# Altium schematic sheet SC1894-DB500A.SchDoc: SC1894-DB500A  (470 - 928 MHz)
size B; Organization: Maxim Integrated; Address1: 160 Rio Robles; Address2: San Jose, CA. 95134; Address3: U.S.A.; Address4: 408-601-1000; Revision: 2.0; SheetNumber: 1; SheetTotal: 1; PageSetup: Record=PageOptions¦CenterHorizontal=True¦CenterVertical=True¦PrintScale=1.12¦XCorrection=1.00¦YCorrection=1.00¦PrintKind=1¦BorderSize=5000000¦LeftOffset=0¦BottomOffset=0¦Orientation=2¦PaperLength=1000¦PaperWidth=1000¦Scale=100¦PaperSource=15¦PrintQuality=600¦MediaType=1¦DitherType=10¦PaperKind=Tabloid¦PrintScaleMode=1
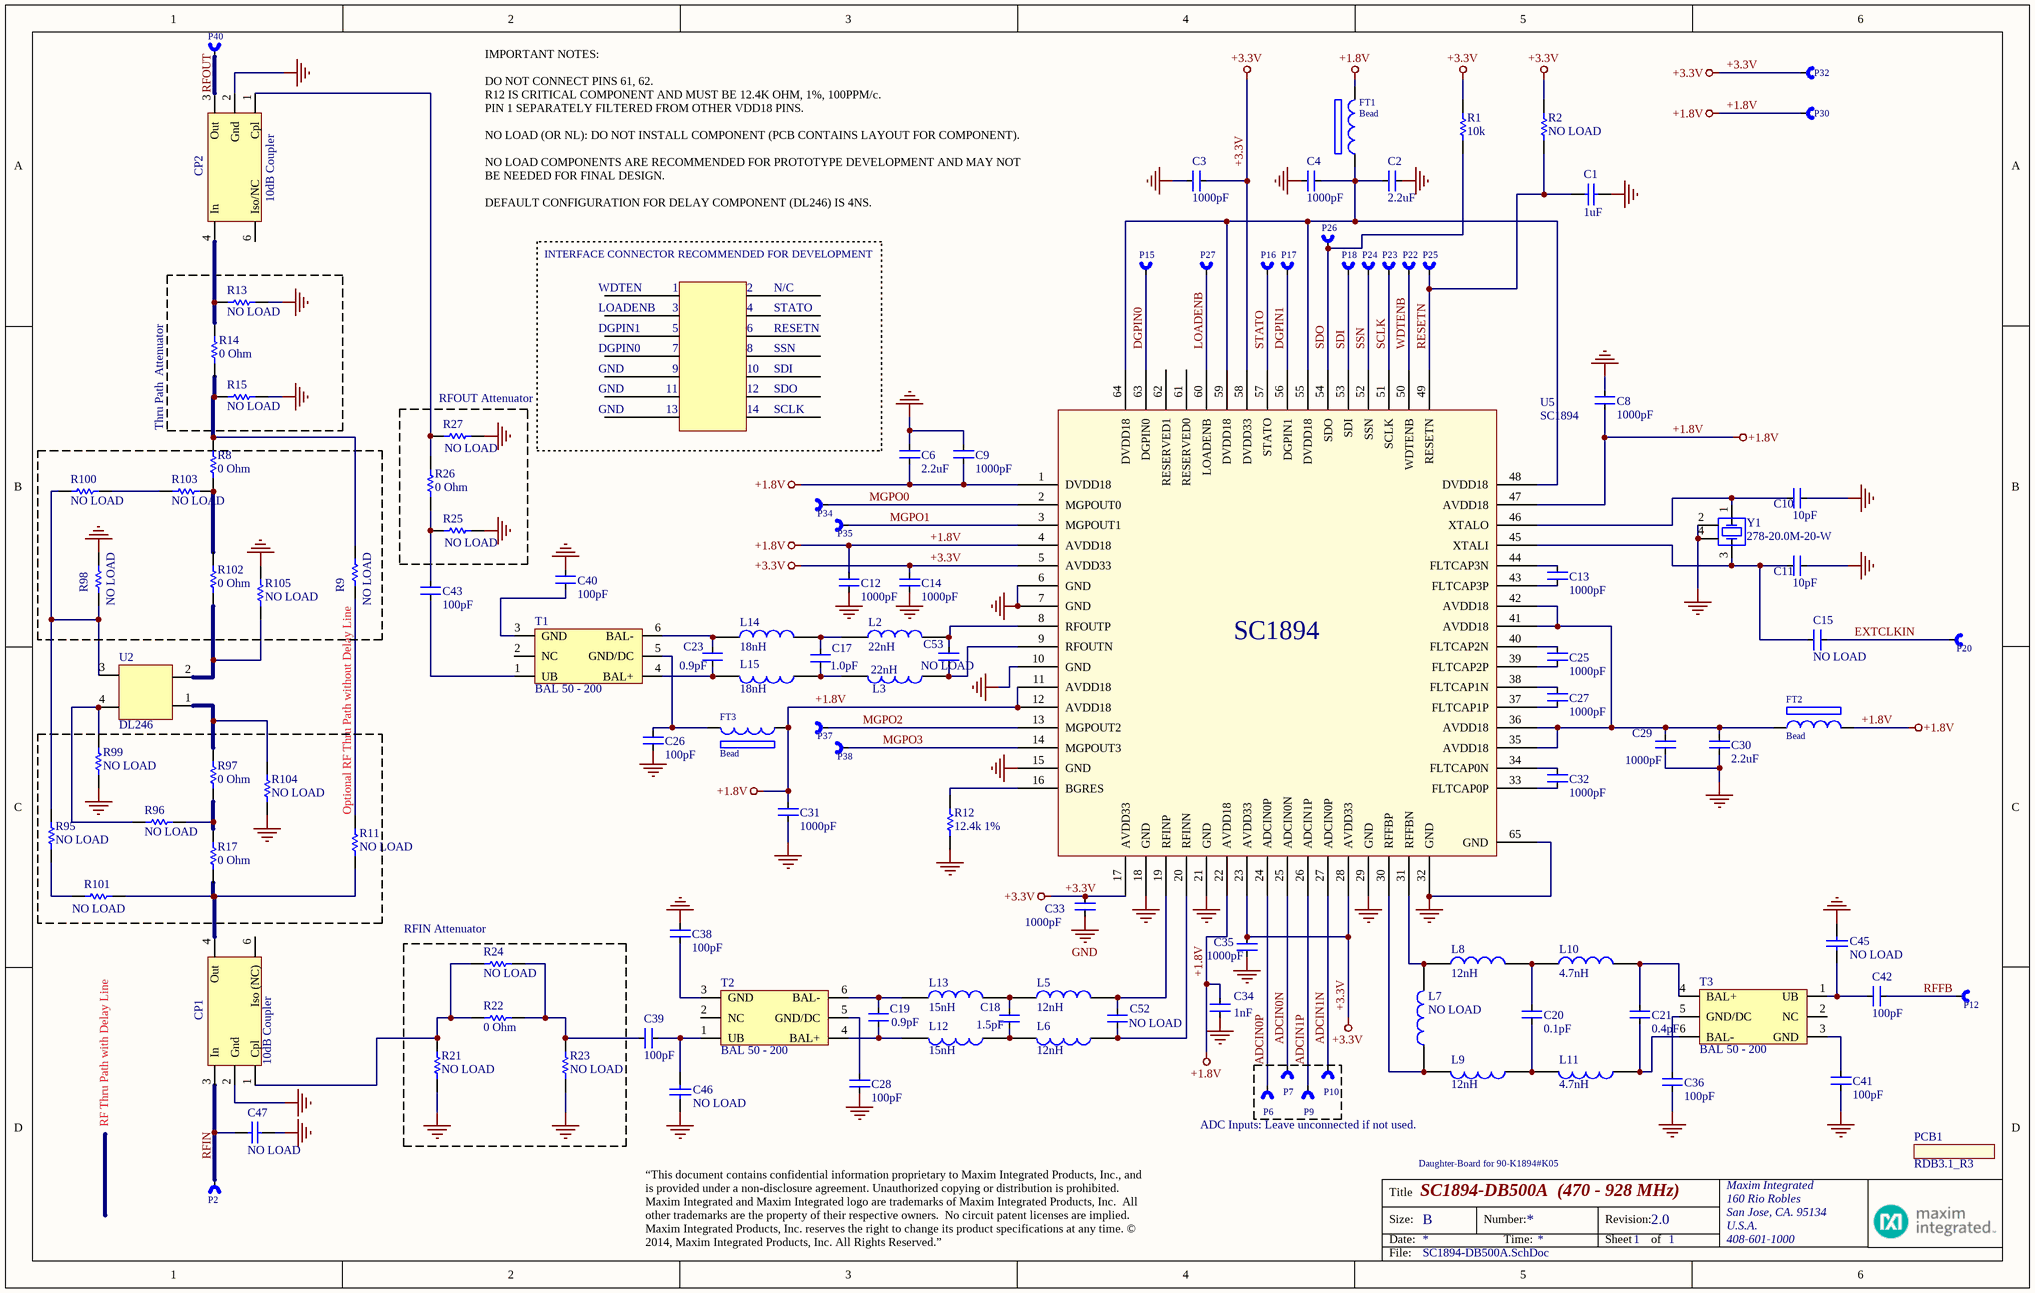
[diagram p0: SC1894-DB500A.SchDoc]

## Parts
C1  1uF  [1608[0603]]
C2  2.2uF  [0603 SMD]
C3  1000pF  [0402 SMD]
C4  1000pF  [0402 SMD]
C6  2.2uF  [0603 SMD]
C8  1000pF  [0402 SMD]
C9  1000pF  [0402 SMD]
C10  10pF  [0402 SMD]
C11  10pF  [0402 SMD]
C12  1000pF  [0402 SMD]
C13  1000pF  [0402 SMD]
C14  1000pF  [0402 SMD]
C15  NO LOAD  [0402 SMD]
C17  1.0pF  [0402 SMD]
C18  1.5pF  [0402 SMD]
C19  0.9pF  [0402 SMD]
C20  0.1pF  [0402 SMD]
C21  0.4pF  [0402 SMD]
C23  0.9pF  [0402 SMD]
C25  1000pF  [0402 SMD]
C26  100pF  [0402 SMD]
C27  1000pF  [0402 SMD]
C28  100pF  [0402 SMD]
C29  1000pF  [0402 SMD]
C30  2.2uF  [0603 SMD]
C31  1000pF  [0402 SMD]
C32  1000pF  [0402 SMD]
C33  1000pF  [0402 SMD]
C34  1nF  [0402 SMD]
C35  1000pF  [0402 SMD]
C36  100pF  [0402 SMD]
C38  100pF  [0402 SMD]
C39  100pF  [0402 SMD]
C40  100pF  [0402 SMD]
C41  100pF  [0402 SMD]
C42  100pF  [0402 SMD]
C43  100pF  [0402 SMD]
C45  NO LOAD  [0402 SMD]
C46  NO LOAD  [0402 SMD]
C47  NO LOAD  [0402 SMD]
C52  NO LOAD  [0402 SMD]
C53  NO LOAD  [0402 SMD]
CP1  10dB Coupler  [DBTC-10-13]
CP2  10dB Coupler  [DBTC-10-13]
FT1  Bead  [0603 SMD]
FT2  Bead  [0603 SMD]
FT3  Bead  [0402 SMD]
L2  22nH  [0402 SMD]
L3  22nH  [0402 SMD]
L5  12nH  [0402 SMD]
L6  12nH  [0402 SMD]
L7  NO LOAD  [0402 SMD]
L8  12nH  [0402 SMD]
L9  12nH  [0402 SMD]
L10  4.7nH  [0402 SMD]
L11  4.7nH  [0402 SMD]
L12  15nH  [0402 SMD]
L13  15nH  [0402 SMD]
L14  18nH  [0402 SMD]
L15  18nH  [0402 SMD]
P2  PORT 1-M  [PORT-1_M-PAD]  (value not drawn)
P6  PORT 1-M  [PORT-1_M-PAD]  (value not drawn)
P7  PORT 1-M  [PORT-1_M-PAD]  (value not drawn)
P9  PORT 1-M  [PORT-1_M-PAD]  (value not drawn)
P10  PORT 1-M  [PORT-1_M-PAD]  (value not drawn)
P12  PORT 1-M  [PORT-1_M-PAD]  (value not drawn)
P15  PORT 1-M  [PORT-1_M-PAD]  (value not drawn)
P16  PORT 1-M  [PORT-1_M-PAD]  (value not drawn)
P17  PORT 1-M  [PORT-1_M-PAD]  (value not drawn)
P18  PORT 1-M  [PORT-1_M-PAD]  (value not drawn)
P20  PORT 1-M  [PORT-1_M-PAD]  (value not drawn)
P22  PORT 1-M  [PORT-1_M-PAD]  (value not drawn)
P23  PORT 1-M  [PORT-1_M-PAD]  (value not drawn)
P24  PORT 1-M  [PORT-1_M-PAD]  (value not drawn)
P25  PORT 1-M  [PORT-1_M-PAD]  (value not drawn)
P26  PORT 1-M  [PORT-1_M-PAD]  (value not drawn)
P27  PORT 1-M  [PORT-1_M-PAD]  (value not drawn)
P30  PORT 1-M  [PORT-1_M-PAD]  (value not drawn)
P32  PORT 1-M  [PORT-1_M-PAD]  (value not drawn)
P34  PORT 1-M  [PORT-1_M-PAD]  (value not drawn)
P35  PORT 1-M  [PORT-1_M-PAD]  (value not drawn)
P37  PORT 1-M  [PORT-1_M-PAD]  (value not drawn)
P38  PORT 1-M  [PORT-1_M-PAD]  (value not drawn)
P40  PORT 1-M  [PORT-1_M-PAD]  (value not drawn)
PCB1  RDB3.1_R3
R1  10k  [0402 SMD]
R2  NO LOAD  [0402 SMD]
R8  0 Ohm  [0402 SMD]
R9  NO LOAD  [0402 SMD]
R11  NO LOAD  [0402 SMD]
R12  12.4k 1%  [0402 SMD]
R13  NO LOAD  [0402 SMD]
R14  0 Ohm  [0402 SMD]
R15  NO LOAD  [0402 SMD]
R17  0 Ohm  [0402 SMD]
R21  NO LOAD  [0402 SMD]
R22  0 Ohm  [0201_SMT]
R23  NO LOAD  [0402 SMD]
R24  NO LOAD  [0201_SMT]
R25  NO LOAD  [0402 SMD]
R26  0 Ohm  [0402 SMD]
R27  NO LOAD  [0402 SMD]
R95  NO LOAD  [0402 SMD]
R96  NO LOAD  [0402 SMD]
R97  0 Ohm  [0402 SMD]
R98  NO LOAD  [0402 SMD]
R99  NO LOAD  [0402 SMD]
R100  NO LOAD  [0402 SMD]
R101  NO LOAD  [0402 SMD]
R102  0 Ohm  [0402 SMD]
R103  NO LOAD  [0402 SMD]
R104  NO LOAD  [0402 SMD]
R105  NO LOAD  [0402 SMD]
T1  BAL 50 - 200  [XFMR-DXP18]
T2  BAL 50 - 200  [XFMR-DXP18]
T3  BAL 50 - 200  [XFMR-DXP18]
U2  DL246  [DL246-A]
U5  SC1894  [SC1894]
Y1  278-20.0M-20-W  [278-20.0M]

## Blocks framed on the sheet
Thru Path  Attenuator: R13-R15
RFOUT Attenuator: R25-R27
Optional RF Thru Path without Delay Line: R11 R17 R95-R97 R99 R101 R104
RFIN Attenuator: R21-R24

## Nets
+1.8V: C6.2 C8.2 C9.2 C12.1 C31.2 C34.2 FT1.2 FT2.2 FT3.1 P30.1(P*) U5.1(DVDD18) U5.4(AVDD18) U5.11(AVDD18) U5.12(AVDD18) U5.22(AVDD18) U5.47(AVDD18)
+3.3V: C3.2 C14.1 C33.1 C35.2 P32.1(P*) R1.2 R2.2 U5.5(AVDD33) U5.17(AVDD33) U5.23(AVDD33) U5.28(AVDD33) U5.58(DVDD33)
GND: C1.1 C2.2 C3.1 C4.1 C6.1 C8.1 C9.1 C10.2 C11.2 C12.2 C14.2 C26.1 C28.1 C29.2 C30.2 C31.1 C33.2 C34.1 C35.1 C36.2 C38.2 C40.2 C41.1 C45.2 C46.2 C47.1 CP1.2(Gnd) CP2.2(Gnd) R12.1 R13.1 R15.1 R21.1 R23.2 R25.2 R27.2 R98.1 R99.1 R104.1 R105.1 U5.6(GND) U5.7(GND) U5.10(GND) U5.15(GND) U5.18(GND) U5.21(GND) U5.29(GND) U5.32(GND) U5.65(GND) Y1.2(SHIELD1) Y1.4(SHIELD2)
ADCIN0N: P7.1(P*) U5.25(ADCIN0N)
ADCIN0P: P6.1(P*) U5.24(ADCIN0P)
ADCIN1N: P10.1(P*) U5.27(ADCIN0P)
ADCIN1P: P9.1(P*) U5.26(ADCIN1P)
DGPIN0: P15.1(P*) U5.63(DGPIN0)
DGPIN1: P17.1(P*) U5.56(DGPIN1)
EXTCLKIN: C15.2 P20.1(P*)
LOADENB: P27.1(P*) U5.60(LOADENB)
MGPO0: P34.1(P*) U5.2(MGPOUT0)
MGPO1: P35.1(P*) U5.3(MGPOUT1)
MGPO2: P37.1(P*) U5.13(MGPOUT2)
MGPO3: P38.1(P*) U5.14(MGPOUT3)
RESETN: C1.2 P25.1(P*) R2.1 U5.49(RESETN)
RFFB: C42.1 P12.1(P*)
RFIN: C47.2 CP1.3(In) P2.1(P*)
RFOUT: CP2.3(Out) P40.1(P*)
SCLK: P23.1(P*) U5.51(SCLK)
SDI: P18.1(P*) U5.53(SDI)
SDO: P26.1(P*) R1.1 U5.54(SDO)
SSN: P24.1(P*) U5.52(SSN)
STATO: P16.1(P*) U5.57(STATO)
WDTENB: P22.1(P*) U5.50(WDTENB)
NetC2_1: C2.1 C4.2 FT1.1 U5.48(DVDD18) U5.55(DVDD18) U5.59(DVDD18) U5.64(DVDD18)
NetC10_1: C10.1 U5.46(XTALO) Y1.1(OSC1)
NetC11_1: C11.1 C15.1 U5.45(XTALI) Y1.3(OSC2)
NetC13_1: C13.1 U5.44(FLTCAP3N)
NetC13_2: C13.2 U5.43(FLTCAP3P)
NetC17_1: C17.1 L2.1 L14.2
NetC17_2: C17.2 L3.2 L15.1
NetC18_1: C18.1 L5.1 L13.2
NetC18_2: C18.2 L6.2 L12.1
NetC19_1: C19.1 L13.1 T2.6(BAL-)
NetC19_2: C19.2 L12.2 T2.4(BAL+)
NetC20_1: C20.1 L9.1 L11.2
NetC20_2: C20.2 L8.2 L10.1
NetC21_1: C21.1 L11.1 T3.6(BAL-)
NetC21_2: C21.2 L10.2 T3.4(BAL+)
NetC23_1: C23.1 L14.1 T1.6(BAL-)
NetC23_2: C23.2 L15.2 T1.4(BAL+)
NetC25_1: C25.1 U5.40(FLTCAP2N)
NetC25_2: C25.2 U5.39(FLTCAP2P)
NetC26_2: C26.2 FT3.2 T1.5(GND/DC)
NetC27_1: C27.1 U5.38(FLTCAP1N)
NetC27_2: C27.2 U5.37(FLTCAP1P)
NetC28_2: C28.2 T2.5(GND/DC)
NetC29_1: C29.1 C30.1 FT2.1 U5.35(AVDD18) U5.36(AVDD18) U5.41(AVDD18) U5.42(AVDD18)
NetC32_1: C32.1 U5.34(FLTCAP0N)
NetC32_2: C32.2 U5.33(FLTCAP0P)
NetC36_1: C36.1 T3.5(GND/DC)
NetC38_1: C38.1 T2.3(GND)
NetC39_1: C39.1 C46.1 T2.1(UB)
NetC39_2: C39.2 R22.1 R23.1 R24.1
NetC40_1: C40.1 T1.3(GND)
NetC41_2: C41.2 T3.3(GND)
NetC42_2: C42.2 C45.1 T3.1(UB)
NetC43_1: C43.1 T1.1(UB)
NetC43_2: C43.2 R25.1 R26.1
NetC52_1: C52.1 L5.2 U5.19(RFINP)
NetC52_2: C52.2 L6.1 U5.20(RFINN)
NetC53_1: C53.1 L3.1 U5.9(RFOUTN)
NetC53_2: C53.2 L2.2 U5.8(RFOUTP)
NetCP1_1: CP1.1(Cpl) R21.2 R22.2 R24.2
NetCP1_4: CP1.4(Out) R11.2 R17.1 R101.1
NetCP2_1: CP2.1(Cpl) R26.2 R27.1
NetCP2_4: CP2.4(In) R13.2 R14.2
NetL7_1: L7.1 L9.2 U5.30(RFFBP)
NetL7_2: L7.2 L8.1 U5.31(RFFBN)
NetR8_1: R8.1 R9.2 R14.1 R15.2
NetR8_2: R8.2 R102.1 R103.1
NetR9_1: R9.1 R11.1
NetR12_2: R12.2 U5.16(BGRES)
NetR17_2: R17.2 R96.2 R97.2
NetR95_1: R95.1 R101.2
NetR95_2: R95.2 R98.2 R100.2 U2.3(2ns_B)
NetR96_1: R96.1 R99.2 U2.4(2ns_A)
NetR97_1: R97.1 R104.2 U2.1(4ns_A)
NetR100_1: R100.1 R103.2
NetR102_2: R102.2 R105.2 U2.2(4ns_B)

Not connected (* = marked no-connect by the designer): CP1 6(Iso_(NC)); CP2 6(Iso/NC); T1 2(NC); T2 2(NC); T3 2(NC); U5 61(RESERVED0) 62(RESERVED1)

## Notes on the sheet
- IMPORTANT NOTES:
  DO NOT CONNECT PINS 61, 62.
  R12 IS CRITICAL COMPONENT AND MUST BE 12.4K OHM, 1%, 100PPM/c.
  PIN 1 SEPARATELY FILTERED FROM OTHER VDD18 PINS.
  NO LOAD (OR NL): DO NOT INSTALL COMPONENT (PCB CONTAINS LAYOUT FOR COMPONENT).
  NO LOAD COMPONENTS ARE RECOMMENDED FOR PROTOTYPE DEVELOPMENT AND MAY NOT BE NEEDED FOR FINAL DESIGN.
  DEFAULT CONFIGURATION FOR DELAY COMPONENT (DL246) IS 4NS.
- INTERFACE CONNECTOR RECOMMENDED FOR DEVELOPMENT
- WDTEN
- 1
- 2
- N/C
- LOADENB
- DGPIN1
- DGPIN0
- GND
- 3
- 5
- 7
- 9
- 4
- 6
- 8
- 10
- STATO
- RESETN
- SSN
- SDI
- 11
- 13
- 12
- 14
- SDO
- SCLK
- RF Thru Path with Delay Line
- ADC Inputs: Leave unconnected if not used.
- Daughter-Board for 90-K1894#K05
- “This document contains confidential information proprietary to Maxim Integrated Products, Inc., and is provided under a non-disclosure agreement. Unauthorized copying or distribution is prohibited.  Maxim Integrated and Maxim Integrated logo are trademarks of Maxim Integrated Products, Inc.  All other trademarks are the property of their respective owners.  No circuit patent licenses are implied.  Maxim Integrated Products, Inc. reserves the right to change its product specifications at any time. © 2014, Maxim Integrated Products, Inc. All Rights Reserved.”

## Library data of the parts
C1 = 1u: 1uF 0603 ceramic capacitor
C2 C6 C30 = Cap 2.2uF 0603: 2.2uF 0603
C3 C4 C8 C9 C12-C14 C25 C27 C29 C31-C35 = Cap 1000pF: 1000pF 0402
C10 C11 C15 = Cap 10pF: 10pF 0402
C17 = Cap 1.0pF: 1.0pF 0402; Part Substitution Allowed?: No
C18 = Cap 1.5pF: 1.5pF 0402; Part Substitution Allowed?: No
C19 C23 = Cap 0.9pF: 0.9pF 0402; Part Substitution Allowed?: No
C20 = Cap 0.1pF: 0.1pF 0402; Part Substitution Allowed?: No
C21 = Cap 0.4pF: 0.4pF 0402; Part Substitution Allowed?: No
C26 C28 C36 C38-C43 = 100pF 0402: 100pF 0402 Murata Capacitor; Manufacturer Part Number 1: GRM1555C1H101JZ01D; Part Substitution Allowed?: No
C45-C47 = Capacitor: Generic Capacitor
C52 C53 = Cap No Load 0402: 0402 Cap No Load
CP1 = DBTC-10-13+: Mini Circuits Coupler 5 - 1000 MHz; Manufacturer 1: Mini-Circuits; Part Substitution Allowed?: No
CP2 = DBTC-10-13+_output: Mini Circuits Coupler 5 - 1000 MHz; Manufacturer 1: Mini-Circuits
FT1 FT2 = Bead 0603: Part Substitution Allowed?: No; Value: 120mH
FT3 = Bead 0402: Bead 0402 470 ohm; Part Substitution Allowed?: No; Value: 470mH
L2 L3 = 22nH: Part Substitution Allowed?: No
L5 L6 L8 L9 = 12nH: Part Substitution Allowed?: No
L7 = Inductor: SMT Inductor
L10 L11 = 4.7nH: Part Substitution Allowed?: No
L12 L13 = 15nH: Part Substitution Allowed?: No
L14 L15 = 18nH: Part Substitution Allowed?: No
P2 P6 P7 P9 P10 P12 P15-P18 P20 P22-P27 P30 P32 P34 P35 P37 P38 P40 = PORT 1-M: Ports of RDB Daughterboards
PCB1 = RDB3.1_R3: Printed Circuit Board (RDB3.1_R3)
R1 = 10k Ohm 0402
R2 R11 R21 R23 = RES NL 0402: NO LOAD RESISTOR 0402
R8 R14 R17 R26 R97 R102 = 0 Ohm 0402
R9 R13 R15 R25 R27 R95 R96 R98-R101 R103-R105 = Resistor: Resistor Generic
R12 = 12.4k Ohm 0402
R22 = 0 Ohm 0201
R24 = RES NL 0201: NO LOAD RESISTOR 0201
T1-T3 = DXP18BN5014T: Murata Balun 50 - 870 MHz   50 - 200; Part Substitution Allowed?: No
U2 = DL246: Kyocera Delay Line DL246; Part Substitution Allowed?: No
U5 = SC1894: SC1894: Adaptive RF Power Amplifier Linearizer; Manufacturer 1: Scintera; Manufacturer Part Number 1: SC1894A-00A00
Y1 = 278-20.0M-20-W: Crystal 20MHz 278-20.0M-20-W; Manufacturer 1: Oscilent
